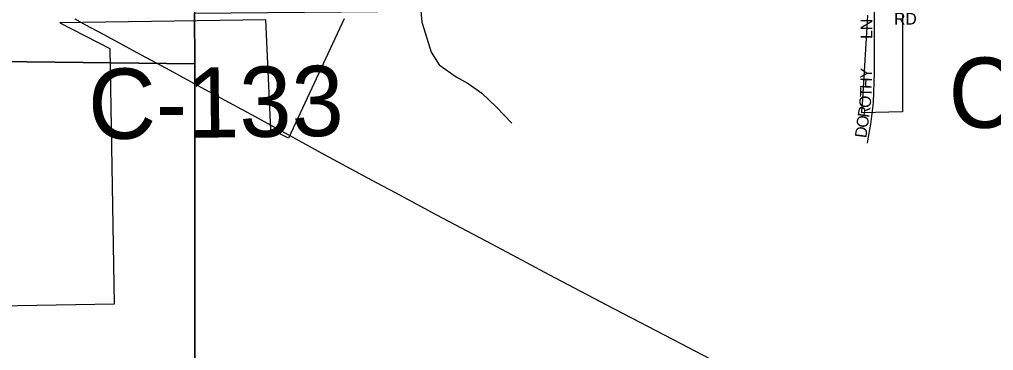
# Model space of a CAD drawing. Extents: x 0 to 680, y 0 to 440.
# Drawn here: x 433.41 to 447.31, y 326.02 to 330.74 of the extents above; entities that cross this region are included whole.
import ezdxf

# ---------------------------------------------------------------- set-up
doc = ezdxf.new("R2010")
doc.units = 0
for name, color, linetype in [('GM_X_City_Street_Text', 7, 'Continuous'), ('GM_X_Corporation', 7, 'Continuous'), ('GM_X_County_Road_Text', 7, 'Continuous'), ('GM_X_Minor_River', 7, 'Continuous'), ('GM_X_Section', 7, 'Continuous'), ('GM_X_State_Route', 7, 'Continuous'), ('GM_X_Township_Subdivision', 7, 'Continuous'), ('GM_X_Township_Subdivision_Text', 7, 'Continuous')]:
    doc.layers.add(name, color=color, linetype=linetype)

msp = doc.modelspace()

# ---------------------------------------------------------------- linework, layer by layer
at = {"layer": 'GM_X_Corporation'}
for points in [[(438.039, 330.747), (437.245, 329.044), (436.993, 329.167), (436.921, 330.731), (433.98, 330.689), (434.694, 330.324), (434.757, 326.68), (427.026, 326.545)], [(446.009, 330.799), (446.009, 329.418), (445.428, 329.408), (445.43, 329.43), (445.436, 329.529), (445.505, 330.628), (445.515, 330.798)]]:
    msp.add_lwpolyline(points, dxfattribs=at)
at = {"layer": 'GM_X_Minor_River'}
msp.add_lwpolyline([(439.127, 330.913), (439.15, 330.699), (439.201, 330.531), (439.283, 330.268), (439.394, 330.092), (439.639, 329.921), (439.811, 329.824), (440.003, 329.687), (440.207, 329.49), (440.431, 329.259)], dxfattribs=at)
at = {"layer": 'GM_X_Section'}
for points in [[(435.703, 347.83), (435.901, 330.824), (435.907, 330.103), (418.362, 330.315), (418.342, 347.899)], [(453.677, 330.985), (453.772, 312.894), (435.908, 312.881), (435.907, 330.103), (435.901, 330.824)], [(418.362, 330.315), (435.907, 330.103), (435.908, 312.881), (435.905, 312.434), (418.332, 312.54)]]:
    msp.add_lwpolyline(points, close=True, dxfattribs=at)
at = {"layer": 'GM_X_State_Route'}
for points in [[(434.197, 330.744), (434.347, 330.66), (434.611, 330.52), (434.777, 330.432)], [(434.777, 330.432), (435.133, 330.237), (435.497, 330.044), (436.044, 329.745), (436.572, 329.458)], [(436.572, 329.458), (436.717, 329.38), (437.036, 329.205)], [(437.036, 329.205), (437.253, 329.087)], [(437.253, 329.087), (437.763, 328.808), (438.072, 328.642), (438.496, 328.413), (438.766, 328.269), (439.356, 327.955), (440.14, 327.541), (440.642, 327.272), (440.96, 327.104), (441.785, 326.67), (442.845, 326.122), (443.261, 325.902)]]:
    msp.add_lwpolyline(points, dxfattribs=at)
at = {"layer": 'GM_X_Township_Subdivision'}
for points in [[(445.591, 329.51), (445.594, 329.556), (445.608, 329.976), (445.608, 330.481), (445.607, 330.879), (445.607, 330.908)], [(445.51, 328.973), (445.534, 329.117), (445.557, 329.243), (445.591, 329.51)]]:
    msp.add_lwpolyline(points, dxfattribs=at)

# ---------------------------------------------------------------- texts
at = {"layer": 'GM_X_City_Street_Text'}
msp.add_text('RD', height=0.1669, rotation=0, dxfattribs=at).set_placement((445.889, 330.663))
at = {"layer": 'GM_X_County_Road_Text'}
for rotation, p in [(0.2762, (446.668, 329.19)), (0.7898, (434.391, 329.029))]:
    msp.add_text('C-133', height=1.0014, rotation=rotation, dxfattribs=at).set_placement(p)
at = {"layer": 'GM_X_Township_Subdivision_Text'}
for s, height, rotation, p in [('LN', 0.1669, 90, (445.578, 330.46)), ('Y', 0.167, 88.4502, (445.573, 329.893)), ('T', 0.167, 88.3727, (445.566, 329.628)), ('H', 0.167, 88.439, (445.569, 329.746)), ('O', 0.167, 84.7106, (445.551, 329.47)), ('R', 0.167, 81.9524, (445.532, 329.331)), ('O', 0.167, 81.9422, (445.511, 329.185)), ('D', 0.167, 81.9317, (445.491, 329.04))]:
    msp.add_text(s, height=height, rotation=rotation, dxfattribs=at).set_placement(p)

doc.saveas('drawing.dxf')
